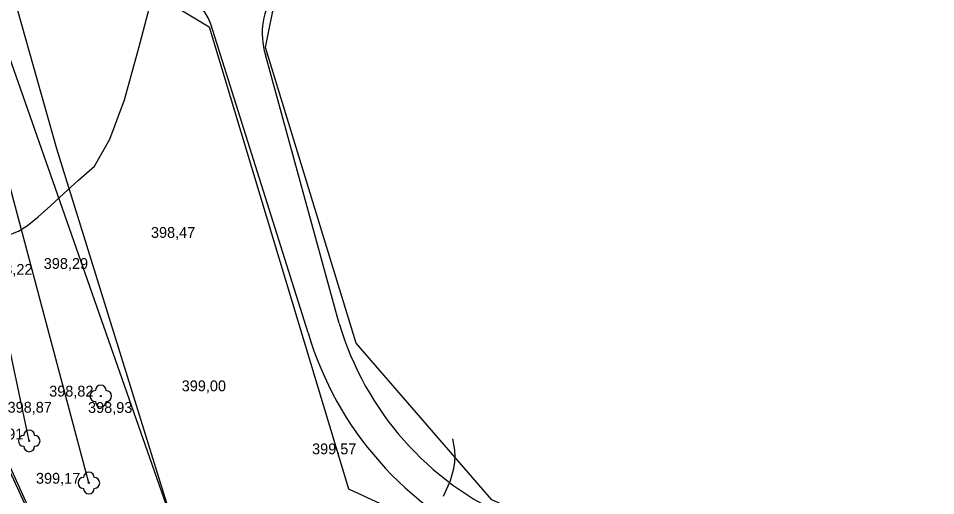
# Model space of a CAD drawing. Extents: x -574342 to -507939, y -1144044 to -1123894.
# Drawn here: x -508411.2 to -508326.5, y -1143303.4 to -1143259.3 of the extents above; entities that cross this region are included whole.
import ezdxf

# ---------------------------------------------------------------- set-up
doc = ezdxf.new("R2010")
doc.units = 0
for name, color, linetype in [('01_PARCELY_NAVRH_PC', 7, 'Continuous'), ('01_PARCELY_NAVRH_ZPF', 7, 'Continuous'), ('01_PARCELY_NAVRH_ŽP', 7, 'Continuous'), ('42', 7, 'Continuous'), ('54', 7, 'Continuous'), ('55', 7, 'Continuous'), ('cesty', 7, 'Continuous'), ('Level 255', 7, 'Continuous'), ('VRST HL', 7, 'Continuous'), ('VRST VEDL', 7, 'Continuous')]:
    doc.layers.add(name, color=color, linetype=linetype)

msp = doc.modelspace()

# ---------------------------------------------------------------- linework, layer by layer
at = {"layer": '01_PARCELY_NAVRH_PC'}
for points in [[(-508258.82, -1143456.75), (-508307.08, -1143410.68), (-508311.31, -1143403.9), (-508344.65, -1143314.04), (-508367.51, -1143303.79), (-508380.03, -1143289.33), (-508388.43, -1143262.01), (-508387.45, -1143257.24), (-508381.42, -1143253.61), (-508401.25, -1143255.47), (-508393.61, -1143260.11), (-508380.74, -1143302.76), (-508356.16, -1143314.16), (-508344.92, -1143326.36), (-508313.43, -1143410.52), (-508253.01, -1143468.5)], [(-508414.34, -1143296.2), (-508410.3, -1143304.94), (-508406.96, -1143310.33), (-508402.64, -1143313.55), (-508394.5, -1143317.14), (-508397.53, -1143325.93), (-508402.47, -1143323.55), (-508407.39, -1143320.93), (-508414.82, -1143312.69)]]:
    msp.add_lwpolyline(points, dxfattribs=at)
at = {"layer": '01_PARCELY_NAVRH_ZPF'}
msp.add_lwpolyline([(-508263.293, -1143480.706), (-508286.971, -1143456.793), (-508322.95, -1143422.01), (-508338.96, -1143386.69), (-508345.08, -1143368.8), (-508351.18, -1143342.58), (-508355.53, -1143335.68), (-508361.58, -1143328.14), (-508368.91, -1143322.84), (-508376.72, -1143318.72), (-508388.31, -1143315.9), (-508393.87, -1143311.09), (-508396.73, -1143306.67), (-508414.23, -1143256.72), (-508401.25, -1143255.47), (-508393.61, -1143260.11), (-508380.74, -1143302.76), (-508356.16, -1143314.16), (-508344.92, -1143326.36), (-508313.43, -1143410.52), (-508253.01, -1143468.5)], dxfattribs=at)
at = {"layer": '01_PARCELY_NAVRH_ŽP'}
msp.add_lwpolyline([(-508338.96, -1143386.69), (-508345.08, -1143368.8), (-508351.18, -1143342.58), (-508355.53, -1143335.68), (-508361.58, -1143328.14), (-508368.91, -1143322.84), (-508376.72, -1143318.72), (-508388.31, -1143315.9), (-508393.87, -1143311.09), (-508396.73, -1143306.67), (-508414.23, -1143256.72), (-508419.24, -1143259.91), (-508420.08, -1143265.35), (-508416.18, -1143288.91), (-508414.34, -1143296.2), (-508410.3, -1143304.94), (-508406.96, -1143310.33), (-508402.64, -1143313.55), (-508394.5, -1143317.14), (-508377.05, -1143323.29), (-508363.05, -1143330.55), (-508352.96, -1143343.32), (-508344.87, -1143376.79)], dxfattribs=at)
at = {"layer": '42'}
msp.add_lwpolyline([(-508320.88, -1143423.96), (-508327.62, -1143411.06), (-508338.78, -1143387.2), (-508344.67, -1143370.01), (-508350.79, -1143346.58), (-508354.96, -1143336.71), (-508361.36, -1143329.02), (-508368.91, -1143322.84), (-508376.72, -1143318.72), (-508388.31, -1143315.9), (-508393.87, -1143311.09), (-508396.73, -1143306.67), (-508407.7, -1143271.35), (-508414.18, -1143248.41), (-508420.68, -1143216.75), (-508423.64, -1143189.02), (-508427.95, -1143159.6), (-508434.68, -1143117.69), (-508439.72, -1143092.94), (-508444.13, -1143060.48), (-508445.89, -1143059.01)], dxfattribs=at)
msp.add_lwpolyline([(-508320.88, -1143423.96), (-508327.62, -1143411.06), (-508338.78, -1143387.2), (-508344.67, -1143370.01), (-508350.79, -1143346.58), (-508354.96, -1143336.71), (-508361.36, -1143329.02), (-508368.91, -1143322.84), (-508376.72, -1143318.72), (-508388.31, -1143315.9), (-508393.87, -1143311.09), (-508396.73, -1143306.67), (-508407.7, -1143271.35), (-508414.18, -1143248.41), (-508420.68, -1143216.75), (-508423.64, -1143189.02), (-508427.95, -1143159.6), (-508434.68, -1143117.69), (-508439.72, -1143092.94), (-508444.13, -1143060.48), (-508445.89, -1143059.01)], dxfattribs=at)
at = {"layer": '54'}
for centre in [(-508403.63, -1143294.2), (-508410.24, -1143298.34), (-508404.73, -1143302.23)]:
    msp.add_circle(centre, 0.05, dxfattribs=at)
for centre, start, end in [((-508403.63, -1143293.7), 0, 180), ((-508404.13, -1143294.2), 90, 270), ((-508403.13, -1143294.2), 270, 90), ((-508403.63, -1143294.7), 180, 0), ((-508410.74, -1143298.34), 90, 270), ((-508410.24, -1143297.84), 0, 180), ((-508409.74, -1143298.34), 270, 90), ((-508410.24, -1143298.84), 180, 0), ((-508404.73, -1143301.73), 0, 180), ((-508405.23, -1143302.23), 90, 270), ((-508404.23, -1143302.23), 270, 90), ((-508404.73, -1143302.73), 180, 0)]:
    msp.add_arc(centre, 0.5, start, end, dxfattribs=at)
at = {"layer": '55'}
msp.add_line((-508404.73, -1143302.23), (-508412.76, -1143272.01), dxfattribs=at)
msp.add_line((-508404.73, -1143302.23), (-508412.76, -1143272.01), dxfattribs=at)
for points in [[(-508410.24, -1143298.34), (-508420.04, -1143252.1), (-508438.58, -1143205.02)], [(-508410.24, -1143298.34), (-508420.04, -1143252.1), (-508438.58, -1143205.02)], [(-508399.15, -1143318.4), (-508408.17, -1143309.19), (-508414.22, -1143295.92)], [(-508399.15, -1143318.4), (-508408.17, -1143309.19), (-508414.22, -1143295.92)]]:
    msp.add_lwpolyline(points, dxfattribs=at)
at = {"layer": 'cesty'}
for p, q in [((-508384.48, -1143288.366), (-508393.274, -1143260.427)), ((-508381.604, -1143287.515), (-508388.431, -1143262.695))]:
    msp.add_line(p, q, dxfattribs=at)
for centre, radius, start, end in [((-508381.719, -1143260.708), 7, 95.33608, 196.49346), ((-508399.986, -1143262.414), 7, 16.49346, 95.33608), ((-508354.277, -1143279.423), 28.5, 196.49346, 246.32125), ((-508354.277, -1143279.423), 31.5, 196.49346, 246.32125)]:
    msp.add_arc(centre, radius, start, end, dxfattribs=at)
at = {"layer": 'VRST HL'}
msp.add_lwpolyline([(-508371.994, -1143303.449), (-508371.539, -1143302.5), (-508371.335, -1143301.993), (-508371.168, -1143301.459), (-508371.038, -1143300.9), (-508370.945, -1143300.314), (-508370.912, -1143299.749), (-508370.939, -1143299.205), (-508371.113, -1143298.157)], dxfattribs=at)
at = {"layer": 'VRST VEDL'}
msp.add_lwpolyline([(-508411.938, -1143279.251), (-508411.241, -1143278.968), (-508410.399, -1143278.435), (-508409.414, -1143277.652), (-508408.285, -1143276.62), (-508407.041, -1143275.493), (-508405.682, -1143274.273), (-508404.207, -1143272.959), (-508402.79, -1143270.483), (-508401.43, -1143266.845), (-508400.128, -1143262.046), (-508399.246, -1143258.76), (-508398.784, -1143256.987), (-508398.743, -1143256.728), (-508398.986, -1143254.926), (-508399.514, -1143251.58), (-508401.137, -1143241.802)], dxfattribs=at)

# ---------------------------------------------------------------- texts
at = {"layer": 'Level 255'}
for s, p in [('398,47', (-508398.995, -1143279.59)), ('398,29', (-508408.895, -1143282.46)), ('398,22', (-508414.025, -1143283)), ('399,00', (-508396.155, -1143293.76)), ('398,82', (-508408.395, -1143294.25)), ('398,87', (-508412.235, -1143295.74)), ('398,93', (-508404.805, -1143295.76)), ('398,91', (-508414.875, -1143298.21)), ('399,57', (-508384.115, -1143299.58)), ('399,17', (-508409.615, -1143302.3))]:
    msp.add_text(s, height=1, dxfattribs=at).set_placement(p)

doc.saveas('drawing.dxf')
